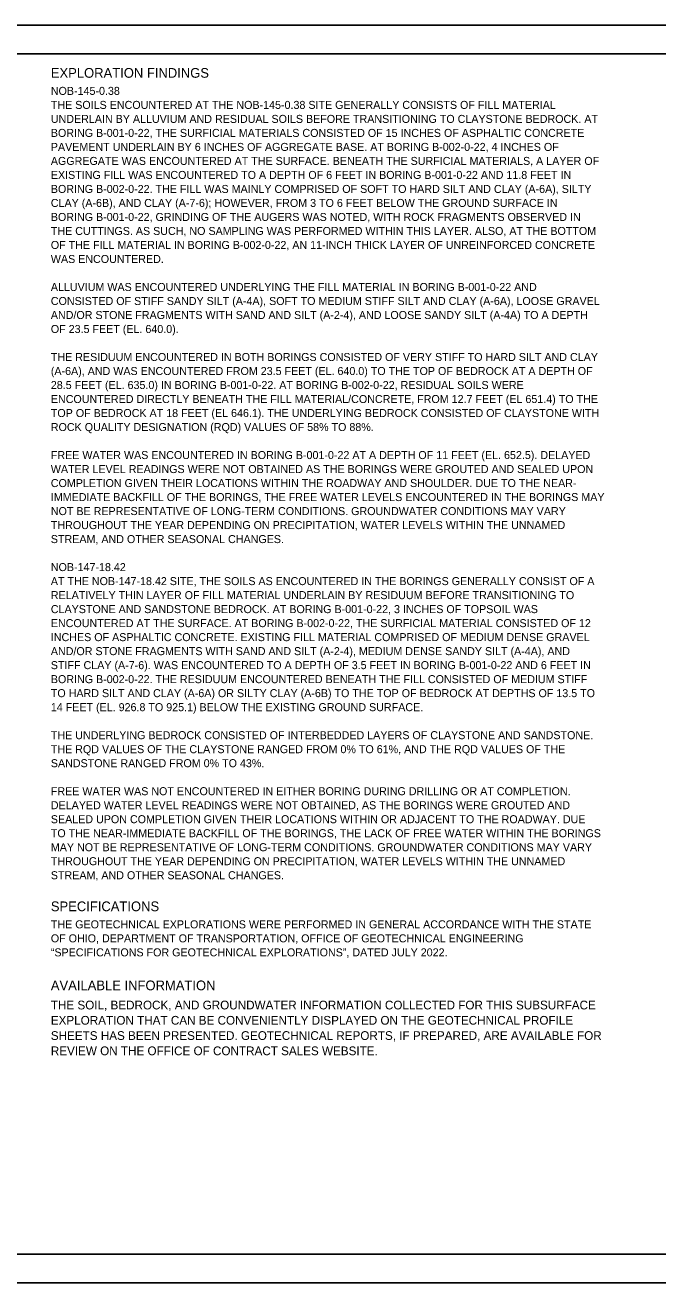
# Model space of a CAD drawing. Extents: x 0 to 34, y 0 to 22.
# Drawn here: x 11.14 to 22.21, y 0 to 22 of the extents above; entities that cross this region are included whole.
import ezdxf

# ---------------------------------------------------------------- set-up
doc = ezdxf.new("R2010")
doc.units = 0
for name, color, linetype in [('Default', 7, 'Continuous'), ('SH_Border', 7, 'Continuous'), ('SH_Cut_Line', 7, 'Continuous'), ('SH_Data', 7, 'Continuous'), ('SH_Text', 7, 'Continuous')]:
    doc.layers.add(name, color=color, linetype=linetype)

msp = doc.modelspace()

# ---------------------------------------------------------------- linework, layer by layer
at = {"layer": 'SH_Border'}
msp.add_lwpolyline([(1.5, 21.5), (33.5, 21.5), (33.5, 0.5), (1.5, 0.5)], close=True, dxfattribs=at)
at = {"layer": 'SH_Cut_Line'}
msp.add_lwpolyline([(0, 0), (34, 0), (34, 22), (0, 22)], close=True, dxfattribs=at)
at = {"layer": 'SH_Data'}
msp.add_line((21.871, 21.5), (11.705, 21.5), dxfattribs=at)

# ---------------------------------------------------------------- texts
at = {"layer": 'Default'}
for s, height, p in [('NOB-145-0.38', 0.14, (11.594, 20.78)), ('THE SOILS ENCOUNTERED AT THE NOB-145-0.38 SITE GENERALLY CONSISTS OF FILL MATERIAL ', 0.14, (11.594, 20.535)), ('UNDERLAIN BY ALLUVIUM AND RESIDUAL SOILS BEFORE TRANSITIONING TO CLAYSTONE BEDROCK. AT ', 0.14, (11.594, 20.29)), ('BORING B-001-0-22, THE SURFICIAL MATERIALS CONSISTED OF 15 INCHES OF ASPHALTIC CONCRETE ', 0.14, (11.594, 20.045)), ('PAVEMENT UNDERLAIN BY 6 INCHES OF AGGREGATE BASE. AT BORING B-002-0-22, 4 INCHES OF ', 0.14, (11.594, 19.8)), ('AGGREGATE WAS ENCOUNTERED AT THE SURFACE. BENEATH THE SURFICIAL MATERIALS, A LAYER OF ', 0.14, (11.594, 19.555)), ('EXISTING FILL WAS ENCOUNTERED TO A DEPTH OF 6 FEET IN BORING B-001-0-22 AND 11.8 FEET IN ', 0.14, (11.594, 19.31)), ('BORING B-002-0-22. THE FILL WAS MAINLY COMPRISED OF SOFT TO HARD SILT AND CLAY (A-6A), SILTY ', 0.14, (11.594, 19.065)), ('CLAY (A-6B), AND CLAY (A-7-6); HOWEVER, FROM 3 TO 6 FEET BELOW THE GROUND SURFACE IN ', 0.14, (11.594, 18.82)), ('BORING B-001-0-22, GRINDING OF THE AUGERS WAS NOTED, WITH ROCK FRAGMENTS OBSERVED IN ', 0.14, (11.594, 18.575)), ('THE CUTTINGS. AS SUCH, NO SAMPLING WAS PERFORMED WITHIN THIS LAYER. ALSO, AT THE BOTTOM ', 0.14, (11.594, 18.33)), ('OF THE FILL MATERIAL IN BORING B-002-0-22, AN 11-INCH THICK LAYER OF UNREINFORCED CONCRETE ', 0.14, (11.594, 18.085)), ('WAS ENCOUNTERED. ', 0.14, (11.594, 17.84)), ('ALLUVIUM WAS ENCOUNTERED UNDERLYING THE FILL MATERIAL IN BORING B-001-0-22 AND ', 0.14, (11.594, 17.35)), ('CONSISTED OF STIFF SANDY SILT (A-4A), SOFT TO MEDIUM STIFF SILT AND CLAY (A-6A), LOOSE GRAVEL ', 0.14, (11.594, 17.105)), ('AND/OR STONE FRAGMENTS WITH SAND AND SILT (A-2-4), AND LOOSE SANDY SILT (A-4A) TO A DEPTH ', 0.14, (11.594, 16.86)), ('OF 23.5 FEET (EL. 640.0).', 0.14, (11.594, 16.615)), ('THE RESIDUUM ENCOUNTERED IN BOTH BORINGS CONSISTED OF VERY STIFF TO HARD SILT AND CLAY ', 0.14, (11.594, 16.125)), ('(A-6A), AND WAS ENCOUNTERED FROM 23.5 FEET (EL. 640.0) TO THE TOP OF BEDROCK AT A DEPTH OF ', 0.14, (11.594, 15.88)), ('28.5 FEET (EL. 635.0) IN BORING B-001-0-22. AT BORING B-002-0-22, RESIDUAL SOILS WERE ', 0.14, (11.594, 15.635)), ('ENCOUNTERED DIRECTLY BENEATH THE FILL MATERIAL/CONCRETE, FROM 12.7 FEET (EL 651.4) TO THE ', 0.14, (11.594, 15.39)), ('TOP OF BEDROCK AT 18 FEET (EL 646.1). THE UNDERLYING BEDROCK CONSISTED OF CLAYSTONE WITH ', 0.14, (11.594, 15.145)), ('ROCK QUALITY DESIGNATION (RQD) VALUES OF 58% TO 88%. ', 0.14, (11.594, 14.9)), ('FREE WATER WAS ENCOUNTERED IN BORING B-001-0-22 AT A DEPTH OF 11 FEET (EL. 652.5). DELAYED ', 0.14, (11.594, 14.41)), ('WATER LEVEL READINGS WERE NOT OBTAINED AS THE BORINGS WERE GROUTED AND SEALED UPON ', 0.14, (11.594, 14.165)), ('COMPLETION GIVEN THEIR LOCATIONS WITHIN THE ROADWAY AND SHOULDER. DUE TO THE NEAR-', 0.14, (11.594, 13.92)), ('IMMEDIATE BACKFILL OF THE BORINGS, THE FREE WATER LEVELS ENCOUNTERED IN THE BORINGS MAY ', 0.14, (11.594, 13.675)), ('NOT BE REPRESENTATIVE OF LONG-TERM CONDITIONS. GROUNDWATER CONDITIONS MAY VARY ', 0.14, (11.594, 13.43)), ('THROUGHOUT THE YEAR DEPENDING ON PRECIPITATION, WATER LEVELS WITHIN THE UNNAMED ', 0.14, (11.594, 13.185)), ('STREAM, AND OTHER SEASONAL CHANGES.', 0.14, (11.594, 12.94)), ('NOB-147-18.42', 0.14, (11.594, 12.45)), ('AT THE NOB-147-18.42 SITE, THE SOILS AS ENCOUNTERED IN THE BORINGS GENERALLY CONSIST OF A ', 0.14, (11.594, 12.205)), ('RELATIVELY THIN LAYER OF FILL MATERIAL UNDERLAIN BY RESIDUUM BEFORE TRANSITIONING TO ', 0.14, (11.594, 11.96)), ('CLAYSTONE AND SANDSTONE BEDROCK. AT BORING B-001-0-22, 3 INCHES OF TOPSOIL WAS ', 0.14, (11.594, 11.715)), ('ENCOUNTERED AT THE SURFACE. AT BORING B-002-0-22, THE SURFICIAL MATERIAL CONSISTED OF 12 ', 0.14, (11.594, 11.47)), ('INCHES OF ASPHALTIC CONCRETE. EXISTING FILL MATERIAL COMPRISED OF MEDIUM DENSE GRAVEL ', 0.14, (11.594, 11.225)), ('AND/OR STONE FRAGMENTS WITH SAND AND SILT (A-2-4), MEDIUM DENSE SANDY SILT (A-4A), AND ', 0.14, (11.594, 10.98)), ('STIFF CLAY (A-7-6). WAS ENCOUNTERED TO A DEPTH OF 3.5 FEET IN BORING B-001-0-22 AND 6 FEET IN ', 0.14, (11.594, 10.735)), ('BORING B-002-0-22. THE RESIDUUM ENCOUNTERED BENEATH THE FILL CONSISTED OF MEDIUM STIFF ', 0.14, (11.594, 10.49)), ('TO HARD SILT AND CLAY (A-6A) OR SILTY CLAY (A-6B) TO THE TOP OF BEDROCK AT DEPTHS OF 13.5 TO ', 0.14, (11.594, 10.245)), ('14 FEET (EL. 926.8 TO 925.1) BELOW THE EXISTING GROUND SURFACE. ', 0.14, (11.594, 10)), ('THE UNDERLYING BEDROCK CONSISTED OF INTERBEDDED LAYERS OF CLAYSTONE AND SANDSTONE. ', 0.14, (11.594, 9.51)), ('THE RQD VALUES OF THE CLAYSTONE RANGED FROM 0% TO 61%, AND THE RQD VALUES OF THE ', 0.14, (11.594, 9.265)), ('SANDSTONE RANGED FROM 0% TO 43%. ', 0.14, (11.594, 9.02)), ('FREE WATER WAS NOT ENCOUNTERED IN EITHER BORING DURING DRILLING OR AT COMPLETION. ', 0.14, (11.594, 8.53)), ('DELAYED WATER LEVEL READINGS WERE NOT OBTAINED, AS THE BORINGS WERE GROUTED AND ', 0.14, (11.594, 8.285)), ('SEALED UPON COMPLETION GIVEN THEIR LOCATIONS WITHIN OR ADJACENT TO THE ROADWAY. DUE ', 0.14, (11.594, 8.04)), ('TO THE NEAR-IMMEDIATE BACKFILL OF THE BORINGS, THE LACK OF FREE WATER WITHIN THE BORINGS ', 0.14, (11.594, 7.795)), ('MAY NOT BE REPRESENTATIVE OF LONG-TERM CONDITIONS. GROUNDWATER CONDITIONS MAY VARY ', 0.14, (11.594, 7.55)), ('THROUGHOUT THE YEAR DEPENDING ON PRECIPITATION, WATER LEVELS WITHIN THE UNNAMED ', 0.14, (11.594, 7.305)), ('STREAM, AND OTHER SEASONAL CHANGES.', 0.14, (11.594, 7.06)), ('THE GEOTECHNICAL EXPLORATIONS WERE PERFORMED IN GENERAL ACCORDANCE WITH THE STATE ', 0.14, (11.594, 6.201)), ('OF OHIO, DEPARTMENT OF TRANSPORTATION, OFFICE OF GEOTECHNICAL ENGINEERING ', 0.14, (11.594, 5.956)), ('“SPECIFICATIONS FOR GEOTECHNICAL EXPLORATIONS”, DATED JULY 2022.', 0.14, (11.594, 5.711)), ('THE SOIL, BEDROCK, AND GROUNDWATER INFORMATION COLLECTED FOR THIS SUBSURFACE ', 0.15273, (11.594, 4.783)), ('EXPLORATION THAT CAN BE CONVENIENTLY DISPLAYED ON THE GEOTECHNICAL PROFILE ', 0.15273, (11.594, 4.516)), ('SHEETS HAS BEEN PRESENTED. GEOTECHNICAL REPORTS, IF PREPARED, ARE AVAILABLE FOR ', 0.15273, (11.594, 4.249)), ('REVIEW ON THE OFFICE OF CONTRACT SALES WEBSITE.', 0.15273, (11.594, 3.982))]:
    msp.add_text(s, height=height, dxfattribs=at).set_placement(p)
at = {"layer": 'SH_Text'}
for s, p in [('EXPLORATION FINDINGS', (11.594, 21.08)), ('SPECIFICATIONS', (11.594, 6.501)), ('AVAILABLE INFORMATION', (11.594, 5.118))]:
    msp.add_text(s, height=0.17, dxfattribs=at).set_placement(p)

doc.saveas('drawing.dxf')
